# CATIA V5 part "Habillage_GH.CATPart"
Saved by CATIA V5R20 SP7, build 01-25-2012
Part number: Habillage_GH
Bounding box of the stored display mesh (mm): x -4 to 4.6, y -68 to 2.853, z -14.552 to -4.448
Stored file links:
  F:\IAO\Catia\Habillage_GH.CATPart
  F:\IAO\Catia\asandre.CATProduct
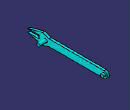
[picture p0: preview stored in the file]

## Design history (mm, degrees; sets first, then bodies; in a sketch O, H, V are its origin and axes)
Set1
  Plane1 "plan.-2": linked copy from another document
  Point1 "G": linked copy from another document
  Point2 "H": linked copy from another document
  Line1 "barre_GH": linked copy from another document
Body1 (main body)
  Sketch1 "Bielle_GH" on Plane1, origin (-2, 0, 0), H (0, 1, 0), V (0, 0, 1)
    construction line L1 (-52, -9.5) -> (0, -9.5)
    point P1 (-52, -9.5)
    point P2 (0, -9.5)
    line L2 (-49.1051, -6.5) -> (0, -6.5)
    line L3 (0, -12.5) -> (-49.1051, -12.5)
    arc A1 centre (0, -9.5) radius 3 from (0, -6.5) to (0, -12.5) cw
    point P3 (-49.1051, -6.5)
    reference projected point E1 (-52, -9.5) from Point1
    reference projected point E2 (0, -9.5) from Point2
    reference projected line E3 (-52, -9.5) -> (0, -9.5) from Line1
    point P6 (-49.1051, -6.5)
    line L4 (-49.1051, -6.5) -> (-54.7433, -4.4479)
    point P7 (-54.7433, -4.4479)
    line L5 (-54.7433, -4.4479) -> (-68, -8)
    point P8 (-68, -8)
    line L6 (-68, -8) -> (-58, -8)
    point P9 (-58, -8)
    line L7 (-58, -8) -> (-58, -9.5)
    point P10 (-58, -9.5)
    reference projected line E4 (-52, -9.5) -> (0, -9.5) from Line1
    reference projected line E5 (-52, -9.5) -> (0, -9.5) from Line1
    reference projected line E6 (-52, -9.5) -> (0, -9.5) from Line1
    reference projected point E7 (-52, -9.5) from Point1
    axis line L8 (0, -9.5) -> (-52, -9.5)
    point P11 (0, -9.5)
    point P12 (-52, -9.5)
    point P13 (-58, -9.5)
    point P14 (-58, -11)
    line L9 (-58, -11) -> (-58, -9.5)
    point P15 (-68, -11)
    line L10 (-68, -11) -> (-58, -11)
    point P16 (-54.7433, -14.5521)
    line L11 (-54.7433, -14.5521) -> (-68, -11)
    line L12 (-49.1051, -12.5) -> (-54.7433, -14.5521)
    reference projected line E8 (-52, -9.5) -> (0, -9.5) from Line1
    reference projected point E9 (-52, -9.5) from Point1
    reference projected point E10 (0, -9.5) from Point2
    distance L1 L2 = 3
    distance L6 E5 = 1.5
    length L7 = 1.5
    length L6 = 10
    distance L7 E7 = 6
    angle L4 L2 = 160
    angle L5 L6 = 15
    length L4 = 6
    tangency: A1 L2, A1 L3
    coincidence: P1 E1, P2 E2, L1 E3, P6 P3, P11 L1, P3 L2, P6 L4, P3 L4, P12 E9, P11 E10
    parallelism: L6 E4, L3 E8
    perpendicularity: L7 E6
    horizontal: L8 H
    symmetry: P10 P13 L8, P9 P14 L8, L7 L9 L8, P8 P15 L8, L6 L10 L8, P7 P16 L8, L5 L11 L8, L4 L12 L8
  Pad1 "Bielle_GH": profile Sketch1, direction (-1, 0, 0), length 2
  Sketch2 "Pivot.D" on Plane1, origin (-2, 0, 0), H (0, 1, 0), V (0, 0, 1)
    circle A1 centre (-52, -9.5) radius 1.5
    point P1 (-52, -9.5)
    reference projected point E1 (-52, -9.5) from Point1
    radius A1 = 1.5
    coincidence: P1 E1
  Pad2 "Pivot.D": profile Sketch2, direction (1, 0, 0), length 6.6
  Sketch3 "pivot.H" on Plane1, origin (-2, 0, 0), H (0, 1, 0), V (0, 0, 1)
    circle A1 centre (0, -9.5) radius 1.5
    point P1 (0, -9.5)
    reference projected point E1 (0, -9.5) from Point2
    radius A1 = 1.5
    coincidence: P1 E1
  Pad3 "Pivot.H": profile Sketch3, direction (1, 0, 0), length 1.9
